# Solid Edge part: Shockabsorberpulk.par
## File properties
Author: Türk
Template: Iso Part.par
Last saved by: Türk
Revision: 22
Application: Solid Edge
Accuracy: 0,990
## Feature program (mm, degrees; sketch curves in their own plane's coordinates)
pattern "PatternOccurrence_1"  XOffset = 72 deg
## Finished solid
Body 1: sheet body, 2 faces, 39 edges, 38 vertices.
  Faces by surface: plane 2
  Edges by curve: line 33, circle 6
Body 2: solid body, 43 faces, 97 edges, 50 vertices.
  Faces by surface: cylinder 23, plane 18, cone 1, torus 1
  Edges by curve: circle 32, line 30, intersection 23, ellipse 12
Bounding box of the edges (mm; curved faces can reach further): 110.000 x 285.130 x 110.000, from (-55, -60, -55) to (55, 225.13, 55).
Cylindrical faces by radius (mm): R2 x2, R5.5 x1, R6 x1, R9.0013 x5, R10.5 x1, R16 x1, R18 x1, R18.3753 x4, R20 x3, R50 x1, R55 x1, R60 x2
Conical faces (half-angle, radius in mm at the cone's reference point): 88.8193 deg R8.5631 x1
Toroidal faces (ring radius, tube radius in mm): R50 r5 x1
Planar faces by outward normal: +x 1, +y 10, +z 1, -x 1, -z 1, oblique 4
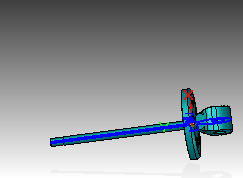
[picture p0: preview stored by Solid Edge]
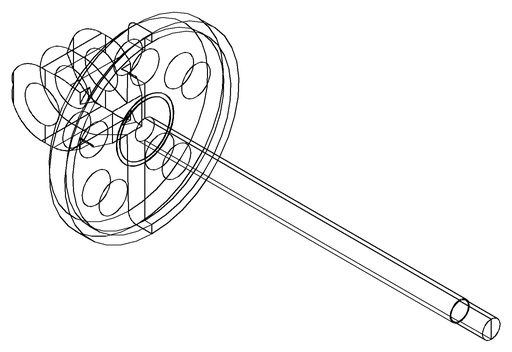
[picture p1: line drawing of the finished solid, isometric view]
